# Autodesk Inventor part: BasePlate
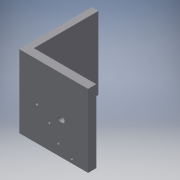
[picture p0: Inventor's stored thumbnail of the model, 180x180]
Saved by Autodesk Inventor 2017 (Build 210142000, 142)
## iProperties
Created: 2017-04
Part Number: BasePlate
Material: Generic
Document SubType Name: Modeling
Designer: 1460374
Density: 1 g/cm^3
Appearance: Default
Author: 1460374
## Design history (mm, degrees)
sketch "Sketch1"
  geometry: L1 (70, 60)-(-70, 60); L2 (-70, 60)-(-70, -60); L3 (-70, -60)-(70, -60); L4 (70, -60)-(70, 60); L5 (70, 60)-(-70, -60); L6 (-70, 60)-(70, -60); 2 further points
  constraints: 12 end point, 2 midpoint, 2 parallel, 1 coincident, 1 horizontal, 1 perpendicular
  dimensions: "d0" = 140 distance of L3.end L2.end; "d1" = 120 distance of L2.end L1.end
extrude "Extrusion1" new body sketch "Sketch1" distance "d2" = 16; taper "d3" = 0 deg
sketch "Sketch2"
  geometry: L1 (-60, 70)-(-60, -70) reference; L2 (-60, -70)-(-76, -70); L3 (-76, -70)-(-76, 70); L4 (-76, 70)-(-60, 70); L5 (-60, 70)-(-60, -70); 1 further point
  constraints: 8 end point, 2 parallel, 1 horizontal, 1 perpendicular
  dimensions: "d4" = 16 distance of L3.end L4.end
extrude "Extrusion2" join sketch "Sketch2" stored distance "d5" = 20; taper "d6" = 0 deg
sketch "Sketch3"
  geometry: L1 (60, -70)-(-76, -70) reference; L2 (60, 70)-(-76, 70) reference; L3 (-76, -70)-(-56, -70); L4 (-56, -70)-(-56, 70); L5 (-56, 70)-(-76, 70); L6 (-76, 70)-(-76, -70); 1 further point
  constraints: 8 end point, 2 parallel, 1 horizontal, 1 perpendicular, 1 point on line
  dimensions: "d7" = 20 distance of L5.end L4.end
extrude "Extrusion3" join sketch "Sketch3" distance "d8" = 120; taper "d9" = 0 deg
sketch "Sketch5"
  geometry: C1 r 3.225 at (-111.686, 10.128) reference; C2 r 3.225 at (-78.937, 26.503) reference; C3 r 3.225 at (-56.718, 59.374) reference; 1 further point
extrude "Extrusion5" cut sketch "Sketch5" stored distance "d12" = 25.4; taper "d13" = 0 deg
sketch "Sketch7"
  geometry: L1 (45.805, 83.881)-(43.956, 83.936) reference; L2 (43.956, 83.936)-(43.927, 82.937) reference; L3 (43.927, 82.937)-(45.775, 82.882) reference; C1 r 3.386 at (42.442, 83.481); C2 r 3.586 at (42.442, 83.481); A1 r 3.386 centre (42.442, 83.481) between (45.775, 82.882) and (45.805, 83.881) reference; A2 r 3.386 centre (42.442, 83.481) between (45.805, 83.881) and (45.775, 82.882) reference; A3 r 3.586 centre (42.442, 83.481) between (45.972, 82.847) and (46.003, 83.905); A4 r 3.586 centre (42.442, 83.481) between (46.003, 83.905) and (45.972, 82.847); 1 further point
  constraints: 8 point on circle, 6 centre point, 6 end point, 2 coincident, 2 concentric, 11 other
  dimensions: "d17" = 0.2 radial gap between concentric circles of A1 A3; "d18" = 0.2 radial gap between concentric circles of A2 A4
extrude "Extrusion7" cut sketch "Sketch7" stored distance "d19" = 25.4; taper "d20" = 0 deg
sketch "Sketch9"
  geometry: L1 (-85.079, 71.815)-(-102.079, 71.815) reference; L2 (-85.079, 88.815)-(-85.079, 71.815) reference; L3 (-102.079, 88.815)-(-85.079, 88.815) reference; L4 (-102.079, 71.815)-(-102.079, 88.815) reference; L5 (-85.079, 80.315)-(-91.429, 80.315); L6 (-85.079, 80.315)-(-78.729, 80.315); L7 (-85.079, 80.315)-(-78.729, 80.315); A1 r 6.35 centre (-85.079, 80.315) between (-86.898, 74.231) and (-86.898, 86.399); A2 r 6.35 centre (-88.718, 80.315) between (-86.898, 86.399) and (-86.898, 74.231); 1 further point
  constraints: 6 end point, 4 point on circle, 3 horizontal, 2 centre point, 1 coincident, 1 collinear, 1 midpoint
  dimensions: "d21" = 6.35 distance of L5.start L5.end; "d22" = 6.35 distance of L5.start L6.end; "d23" = 0 distance between parallel lines of L6 L7 (derived)
extrude "Extrusion8" cut sketch "Sketch9" distance "d24" = 20.6375; taper "d25" = 0 deg
thicken "Thicken1" dims "d26" = 37.7952, "d27" = 37.7952
thicken "Thicken2" dims "d28" = 41.8084, "d29" = 41.8084
thicken "Thicken3" dims "d30" = 32.4104, "d31" = 32.4104
body "Solid1"
node "Reference10"
node "Reference11"
node "Reference12"
node "Reference14"
node "Reference15"
node "Reference16"
node "Reference17"
